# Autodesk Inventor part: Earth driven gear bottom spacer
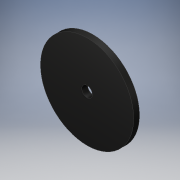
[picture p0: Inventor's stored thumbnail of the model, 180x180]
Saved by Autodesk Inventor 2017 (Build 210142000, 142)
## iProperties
Created: 2016-07
Part Number: Earth driven gear bottom spacer
Material: Generic
Document SubType Name: Modeling
Designer: Stan
Density: 1 g/cm^3
Appearance: Glossy - Black
Author: Stan
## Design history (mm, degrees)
sketch "Sketch1"
  geometry: C1 r 25.4 at (0, 0); C2 r 2.921 at (0, 0); 1 further point
  constraints: 2 centre point, 2 coincident
  dimensions: "d0" = 50.8 diameter of C1; "d1" = 5.842 diameter of C2
extrude "Extrusion1" new body sketch "Sketch1" distance "d2" = 3.175; taper "d3" = 0 deg
body "Solid1"
